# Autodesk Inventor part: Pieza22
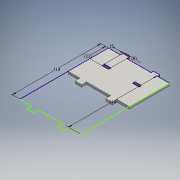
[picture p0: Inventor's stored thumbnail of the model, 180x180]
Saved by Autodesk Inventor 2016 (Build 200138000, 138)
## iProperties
Created: 2016-06
Part Number: Pieza22
Material: Genérico
Document SubType Name: Modeling
Designer: adm
Density: 1 g/cm^3
Appearance: Valor por defecto
Author: adm
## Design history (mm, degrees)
sketch "Boceto1"
  geometry: L1 (-38, -25)-(-38, 25); L2 (38, 25)-(38, -25); L3 (38, -25)-(-38, 25); L4 (-38, -25)-(38, 25); L5 (-15, 25)-(-15, 28); L6 (-15, 28)-(-23, 28); L7 (-23, 28)-(-23, 25); L8 (15, 25)-(15, 28); L9 (15, 28)-(23, 28); L10 (23, 28)-(23, 25); L11 (23, -31)-(23, -25); L12 (15, -25)-(15, -31); L13 (15, -31)-(23, -31); L14 (-15, -25)-(-15, -31); L15 (-23, -31)-(-23, -25); L16 (-15, -31)-(-23, -31); L17 (-38, 25)-(-23, 25); L18 (-15, 25)-(15, 25); L19 (23, 25)-(38, 25); L20 (-23, -25)-(-38, -25); L21 (38, -25)-(23, -25); L22 (15, -25)-(-15, -25); 1 further point
  constraints: 44 end point, 12 parallel, 5 horizontal, 4 vertical, 3 perpendicular, 2 horizontal alignment, 2 midpoint
  dimensions: "d0" = 50 distance of L2.start L2.end; "d1" = 76 distance of L2.end L1.start; "d2" = 30 distance between parallel lines of L8 L5; "d3" = 8 distance of L8.end L9.end; "d4" = 8 distance of L5.end L6.end; "d5" = 15 distance from line of point (0, 0) L8; "d6" = 3 distance of L8.start L8.end; "d7" = 3 distance of L5.start L5.end; "d16" = 6 distance of L14.start L14.end; "d17" = 6 distance of L12.start L12.end
extrude "Extrusión1" new body sketch "Boceto1" distance "d8" = 3; taper "d9" = 0 deg
sketch "Boceto2"
  geometry: L1 (-23, 5)-(-15, 5); L2 (-15, 5)-(-15, 2); L3 (-15, 2)-(-23, 2); L4 (-23, 2)-(-23, 5); L5 (-38, 25)-(-38, -25) reference; L6 (15, 25)-(-15, 25) reference; L7 (0, 0)-(0, 13.533); L8 (23, 5)-(15, 5); L9 (15, 5)-(15, 2); L10 (15, 2)-(23, 2); L11 (23, 2)-(23, 5)
  constraints: 18 end point, 4 symmetric about line, 2 parallel, 1 horizontal, 1 perpendicular, 1 vertical
  dimensions: "d10" = 8 distance of L2.end L3.end; "d11" = 15 distance between parallel lines of L5 L4; "d12" = 20 distance between parallel lines of L6 L1; "d13" = 3 distance of L1.end L2.end
extrude "Extrusión2" cut sketch "Boceto2" distance "d14" = 10; taper "d15" = 0 deg
sketch "Boceto3"
  geometry: L1 (-38, 25)-(-38, -85); L2 (38, 25)-(38, -85); L3 (-38, -85)-(-23, -85); L4 (-23, -85)-(-23, -91); L5 (-23, -91)-(-15, -91); L6 (-15, -91)-(-15, -85); L7 (-15, -85)-(15, -85); L8 (15, -85)-(15, -91); L9 (15, -91)-(23, -91); L10 (23, -91)-(23, -85); L11 (23, -85)-(38, -85); L12 (-23, 2)-(-23, 5) reference; L13 (-15, 2)-(-23, 2) reference; L14 (-23, 5)-(-23, 2); L15 (-23, 2)-(-15, 2); L16 (-15, 2)-(-15, 5) reference; L17 (-15, 2)-(-15, 5); L18 (-15, 5)-(-23, 5) reference; L19 (-15, 5)-(-23, 5); L20 (15, 2)-(15, 5) reference; L21 (15, 5)-(15, 2); L22 (15, 2)-(23, 2) reference; L23 (15, 2)-(23, 2); L24 (23, 5)-(23, 2) reference; L25 (23, 2)-(23, 5); L26 (23, 5)-(15, 5); L27 (-38, 25)-(-23, 25); L28 (-23, 28)-(-23, 25) reference; L29 (-23, 25)-(-23, 28); L30 (-23, 28)-(-15, 28); L31 (-15, 28)-(-15, 25); L32 (-15, 25)-(15, 25); L33 (15, 28)-(15, 25) reference; L34 (15, 25)-(15, 28); L35 (23, 28)-(15, 28) reference; L36 (15, 28)-(23, 28); L37 (23, 28)-(23, 25); L38 (38, 25)-(23, 25) reference; L39 (23, 25)-(38, 25); 1 further point
  constraints: 56 end point, 15 perpendicular, 2 collinear, 2 horizontal, 2 vertical, 1 point on line
  dimensions: "d18" = 110 distance of L1.start L1.end; "d19" = 110 distance of L2.start L2.end; "d20" = 15 distance from line of L1 L12.end; "d21" = 8 distance of L16.end L12.end (derived); "d22" = 23 distance between parallel lines of L13 L27 (derived)
node "Sólido1"
